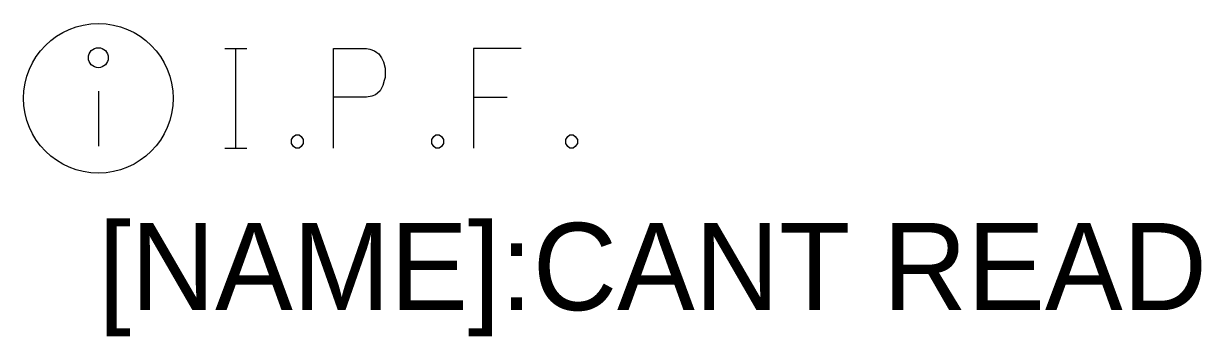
# Model space of a CAD drawing. Extents: x 1386013 to 1389776, y 604170 to 607009.
# Drawn here: x 1386090.04 to 1386108.94, y 604612.63 to 604617.66 of the extents above; entities that cross this region are included whole.
import ezdxf

# ---------------------------------------------------------------- set-up
doc = ezdxf.new("R2010")
doc.units = 0
doc.layers.add('SC_Scratch1', color=7, linetype='Continuous')
doc.layers.add('SV_X_Mon_Cells_Found_Text', color=7, linetype='Continuous')

msp = doc.modelspace()

# ---------------------------------------------------------------- linework, layer by layer
at = {"layer": 'SC_Scratch1'}
msp.add_line((1386091.239, 604616.574), (1386091.239, 604615.691), dxfattribs=at)
for points in [[(1386093.269, 604617.257), (1386093.622, 604617.257)], [(1386093.446, 604615.657), (1386093.446, 604617.257)], [(1386095.011, 604615.657), (1386095.011, 604617.257), (1386095.54, 604617.257), (1386095.595, 604617.245), (1386095.672, 604617.219), (1386095.706, 604617.194), (1386095.738, 604617.169), (1386095.783, 604617.106), (1386095.816, 604617.043), (1386095.838, 604616.942), (1386095.838, 604616.791), (1386095.827, 604616.741), (1386095.805, 604616.665), (1386095.761, 604616.577), (1386095.716, 604616.539), (1386095.683, 604616.514), (1386095.628, 604616.489), (1386095.54, 604616.476), (1386095.011, 604616.476)], [(1386098.02, 604617.257), (1386097.26, 604617.257), (1386097.26, 604615.657)], [(1386097.26, 604616.476), (1386097.8, 604616.476)], [(1386094.405, 604615.871), (1386094.46, 604615.871), (1386094.493, 604615.846), (1386094.526, 604615.796), (1386094.526, 604615.733), (1386094.493, 604615.682), (1386094.46, 604615.657), (1386094.405, 604615.657), (1386094.372, 604615.682), (1386094.339, 604615.733), (1386094.339, 604615.796), (1386094.372, 604615.846), (1386094.405, 604615.871)], [(1386096.653, 604615.871), (1386096.709, 604615.871), (1386096.742, 604615.846), (1386096.775, 604615.796), (1386096.775, 604615.733), (1386096.742, 604615.682), (1386096.709, 604615.657), (1386096.653, 604615.657), (1386096.62, 604615.682), (1386096.587, 604615.733), (1386096.587, 604615.796), (1386096.62, 604615.846), (1386096.653, 604615.871)], [(1386098.803, 604615.871), (1386098.858, 604615.871), (1386098.891, 604615.846), (1386098.924, 604615.796), (1386098.924, 604615.733), (1386098.891, 604615.682), (1386098.858, 604615.657), (1386098.803, 604615.657), (1386098.77, 604615.682), (1386098.737, 604615.733), (1386098.737, 604615.796), (1386098.77, 604615.846), (1386098.803, 604615.871)], [(1386093.269, 604615.657), (1386093.622, 604615.657)]]:
    msp.add_lwpolyline(points, dxfattribs=at)
for centre, radius in [((1386091.239, 604616.457), 1.2), ((1386091.239, 604617.109), 0.16)]:
    msp.add_circle(centre, radius, dxfattribs=at)

# ---------------------------------------------------------------- texts
at = {"layer": 'SV_X_Mon_Cells_Found_Text'}
msp.add_text('[NAME]:CANT READ', height=1.4, dxfattribs=at).set_placement((1386091.239, 604613.057))

doc.saveas('drawing.dxf')
